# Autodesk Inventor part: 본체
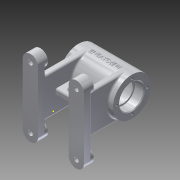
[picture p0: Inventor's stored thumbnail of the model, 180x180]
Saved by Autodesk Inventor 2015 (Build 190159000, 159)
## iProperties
Created: 2015-11
Part Number: 본체
Material: 알루미늄 6061
Document SubType Name: Modeling
Designer: Administrator
Density: 2.7 g/cm^3
Appearance: 알루미늄 - 평지
Author: Administrator
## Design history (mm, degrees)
sketch "스케치8"
  geometry: L1 (40, 40)-(40, -40); L2 (20, 40)-(20, -40); L3 (-20, 40)-(-20, -40); L4 (-40, 40)-(-40, -40); A1 r 10 centre (30, 40) between (40, 40) and (20, 40); A2 r 10 centre (30, -40) between (20, -40) and (40, -40); A3 r 10 centre (-30, 40) between (-20, 40) and (-40, 40); A4 r 10 centre (-30, -40) between (-40, -40) and (-20, -40); 3 further points
  constraints: 8 end point, 8 point on circle, 8 tangent, 4 centre point, 2 parallel, 2 vertical, 1 equal radius, 1 horizontal alignment, 1 vertical alignment
  dimensions: "d54" = 10 radius of A1; "d57" = 0 distance from line of point (40, 0) L1
extrude "돌출3" new body sketch "스케치8" distance "d63" = 10; taper "d64" = 0 deg
sketch "스케치9"
  geometry: L1 (-40, -40)-(-40, 40) reference; L2 (-20, 40)-(-20, -40) reference; L3 (20, -40)-(20, 40) reference; L4 (40, 40)-(40, -40) reference; A1 r 10 centre (-30, 40) between (-20, 40) and (-40, 40) reference; A2 r 10 centre (-30, -40) between (-40, -40) and (-20, -40) reference; A3 r 10 centre (30, -40) between (20, -40) and (40, -40) reference; A4 r 10 centre (30, 40) between (40, 40) and (20, 40) reference; 5 further points
  constraints: 4 coincident, 4 horizontal alignment, 8 other
extrude "돌출4" join sketch "스케치9" distance "d65" = 3; taper "d66" = 0 deg
fillet "모깎기2" dims "d67" = 2
sketch "스케치10"
  geometry: L1 (22, 10)-(38, 10) reference; L2 (40, 8)-(40, 0) reference; L3 (40, 0)-(20, 0) reference; L4 (20, 0)-(20, 8) reference; L5 (-38, 10)-(-22, 10) reference; L6 (-20, 8)-(-20, 0) reference; L7 (-20, 0)-(-40, 0) reference; L8 (-40, 0)-(-40, 8) reference; L9 (0, 0)-(0, 68); L10 (35, 68)-(-35, 68); L11 (-35, 68)-(-35, 93); L12 (-35, 93)-(35, 93); L13 (35, 93)-(35, 68); A1 r 2 centre (22, 8) between (22, 10) and (20, 8) reference; A2 r 2 centre (38, 8) between (40, 8) and (38, 10) reference; A3 r 2 centre (-38, 8) between (-38, 10) and (-40, 8) reference; A4 r 2 centre (-22, 8) between (-20, 8) and (-22, 10) reference
  constraints: 10 end point, 2 perpendicular, 2 vertical
  dimensions: "d70" = 68 distance of L9.start L9.end; "d71" = 35 distance of L9.end L10.start; "d72" = 70 distance of L10.start L10.end; "d73" = 25 distance of L10.end L11.end
revolve "회전1" sketch "스케치10" stored, may be unused: angle "d74" = 90 deg
sketch "스케치11"
  geometry: L1 (-31.34, -58)-(31.34, -58) reference; L2 (31.34, -58)-(31.34, -55) reference; L3 (31.34, -55)-(48.66, -55) reference; L4 (48.66, -55)-(48.66, -68) reference; L5 (48.66, -68)-(-48.66, -68) reference; L6 (-48.66, -68)-(-48.66, -55) reference; L7 (-48.66, -55)-(-31.34, -55) reference; L8 (-31.34, -55)-(-31.34, -58) reference; C1 r 25 at (0, 0) reference; A1 r 20 centre (0, 0) between (-20, 0) and (0, 20); 3 further points
  constraints: 4 point on circle, 1 centre point, 1 coincident
  dimensions: "d75" = 40 diameter of A1
hole "구멍6" sketch "스케치11" at (-20, 0), (0, 20), (20, 0), (0, -20) diameter "d76" = 3.242; stored, may be unused: countersink angle "d80" = 90 deg, drill point angle "d82" = 118 deg; dims "d77" = 8, "d78" = 4, "d79" = 2, "d81" = 10
sketch "스케치12"
  geometry: L1 (-31.34, -58)-(31.34, -58) reference; L2 (31.34, -58)-(31.34, -55) reference; L3 (31.34, -55)-(48.66, -55) reference; L4 (48.66, -55)-(48.66, -68) reference; L5 (48.66, -68)-(-48.66, -68) reference; L6 (-48.66, -68)-(-48.66, -55) reference; L7 (-48.66, -55)-(-31.34, -55) reference; L8 (-31.34, -55)-(-31.34, -58) reference; C1 r 1.621 at (20, 0) reference; C2 r 1.621 at (-20, 0) reference; C3 r 1.621 at (0, 20) reference; C4 r 1.621 at (0, -20) reference; C5 r 25 at (0, 0) reference; 1 further point
hole "구멍7" sketch "스케치12" at (0, 0) diameter "d83" = 32; stored, may be unused: countersink angle "d87" = 90 deg, drill point angle "d89" = 0 deg; dims "d84" = 8, "d85" = 4, "d86" = 2, "d88" = 12
sketch "스케치13"
  geometry: L1 (-32.859, -58)-(32.859, -58) reference; L2 (32.859, -58)-(32.859, -55) reference; L3 (32.859, -55)-(47.141, -55) reference; L4 (47.141, -55)-(47.141, -68) reference; L5 (47.141, -68)-(-47.141, -68) reference; L6 (-47.141, -68)-(-47.141, -55) reference; L7 (-47.141, -55)-(-32.859, -55) reference; L8 (-32.859, -55)-(-32.859, -58) reference; C1 r 16 at (0, 0) reference; C2 r 25 at (0, 0) reference; 1 further point
hole "구멍8" sketch "스케치13" at (0, 0) diameter "d90" = 28; stored, may be unused: countersink angle "d94" = 90 deg, drill point angle "d96" = 0 deg; dims "d91" = 8, "d92" = 4, "d93" = 2, "d95" = 2
sketch "스케치14"
  geometry: L1 (-44.359, -55)-(-35.641, -55) reference; L2 (-35.641, -55)-(-35.641, -58.268) reference; L3 (-35.641, -58.268)-(35.641, -58.268) reference; L4 (35.641, -58.268)-(35.641, -55) reference; L5 (35.641, -55)-(44.359, -55) reference; L6 (44.359, -55)-(44.359, -68) reference; L7 (44.359, -68)-(-44.359, -68) reference; L8 (-44.359, -68)-(-44.359, -55) reference; C1 r 14 at (0, 0) reference; C2 r 25 at (0, 0) reference; 1 further point
hole "구멍9" sketch "스케치14" at (0, 0) diameter "d97" = 42; stored, may be unused: countersink angle "d101" = 90 deg, drill point angle "d103" = 0 deg; dims "d98" = 8, "d99" = 4, "d100" = 2, "d102" = 42
chamfer "모따기3" distance "d104" = 1; stored, may be unused: second distance "d105" = 2, angle "d106" = 45 deg
chamfer "모따기4" distance "d107" = 1; stored, may be unused: second distance "d108" = 2, angle "d109" = 45 deg
fillet "모깎기3" dims "d110" = 3
node "작업 평면5"
  node "작업 평면4"
sketch "스케치15"
  geometry: L1 (35, -25)-(-35, -25) reference; L2 (35, 25)-(35, -25) reference; L3 (35, 25)-(-35, 25) reference; L4 (-35, 25)-(-35, -25) reference; C1 r 5 at (0, 0); 1 further point
  constraints: 1 centre point, 1 coincident
  dimensions: "d112" = 10 diameter of C1
extrude "돌출5" join sketch "스케치15" stored distance "d113" = 70; taper "d114" = 0 deg
fillet "모깎기4" dims "d115" = 2
sketch "스케치16"
  geometry: C1 r 5 at (0, 0) reference; 1 further point
hole "구멍10" sketch "스케치16" at (0, 0) diameter "d116" = 5.188; stored, may be unused: countersink angle "d120" = 90 deg, drill point angle "d122" = 0 deg; dims "d117" = 15, "d118" = 4, "d119" = 2, "d121" = 15
sketch "스케치17"
  geometry: L1 (0, 8)-(80, 8) reference; L2 (80, 0)-(80, 8) reference; L3 (80, 0)-(0, 0) reference; L4 (0, 0)-(0, 8) reference; L5 (0, 8)-(0, 13) reference; L6 (80, 8)-(80, 13) reference; L7 (40, 0)-(15, 0); L8 (80, 0)-(0, 0) reference; L9 (15, 0)-(15, 67); L10 (15, 0)-(65, 0); L11 (65, 0)-(65, 67); L12 (65, 67)-(53.394, 48.192); L13 (53.394, 48.192)-(40, 44.602); L14 (40, 44.602)-(25.54, 50.049); L15 (25.54, 50.049)-(15, 67); C1 r 25 at (40, 68) reference; C2 r 20.236 at (40, 68) reference
  constraints: 16 end point, 2 point on line, 1 perpendicular
  dimensions: "d126" = 50 distance of L7.end L10.end; "d127" = 90 deg angle of L11 L10
extrude "돌출6" join sketch "스케치17" distance "d128" = 8; taper "d129" = 0 deg
fillet "모깎기6" dims "d131" = 2
sketch "스케치18"
  geometry: L1 (8, -65)-(4, -65) reference; L2 (2, -63)-(2, -17) reference; L3 (4, -15)-(8, -15) reference; L4 (10, -17)-(10, -63) reference; L5 (58, -17)-(58, -63) reference; L6 (56, -65)-(52, -65) reference; L7 (50, -63)-(50, -17) reference; L8 (52, -15)-(56, -15) reference; C1 r 10 at (0, 0) reference; C2 r 10 at (0, -80) reference; C3 r 10 at (60, -80) reference; C4 r 10 at (60, 0) reference; A1 r 2 centre (8, -63) between (8, -65) and (10, -63) reference; A2 r 2 centre (4, -63) between (2, -63) and (4, -65) reference; A3 r 2 centre (4, -17) between (4, -15) and (2, -17) reference; A4 r 2 centre (8, -17) between (10, -17) and (8, -15) reference; A5 r 2 centre (56, -17) between (58, -17) and (56, -15) reference; A6 r 2 centre (56, -63) between (56, -65) and (58, -63) reference; A7 r 2 centre (52, -63) between (50, -63) and (52, -65) reference; A8 r 2 centre (52, -17) between (52, -15) and (50, -17) reference; 1 further point
hole "구멍11" sketch "스케치18" at (60, 0), (0, 0) diameter "d132" = 12; stored, may be unused: countersink angle "d136" = 90 deg, drill point angle "d138" = 0 deg; dims "d133" = 3, "d134" = 4, "d135" = 2, "d137" = 4
sketch "스케치19"
  geometry: L1 (8, 15)-(4, 15) reference; L2 (2, 17)-(2, 63) reference; L3 (4, 65)-(8, 65) reference; L4 (10, 63)-(10, 17) reference; L5 (58, 63)-(58, 17) reference; L6 (56, 15)-(52, 15) reference; L7 (50, 17)-(50, 63) reference; L8 (52, 65)-(56, 65) reference; C1 r 6 at (60, 80) reference; C2 r 6 at (0, 80) reference; C3 r 10 at (0, 80) reference; C4 r 10 at (0, 0) reference; C5 r 10 at (60, 0) reference; C6 r 10 at (60, 80) reference; A1 r 2 centre (8, 17) between (8, 15) and (10, 17) reference; A2 r 2 centre (4, 17) between (2, 17) and (4, 15) reference; A3 r 2 centre (4, 63) between (4, 65) and (2, 63) reference; A4 r 2 centre (8, 63) between (10, 63) and (8, 65) reference; A5 r 2 centre (56, 63) between (58, 63) and (56, 65) reference; A6 r 2 centre (56, 17) between (56, 15) and (58, 17) reference; A7 r 2 centre (52, 17) between (50, 17) and (52, 15) reference; A8 r 2 centre (52, 63) between (52, 65) and (50, 63) reference; 1 further point
hole "구멍12" sketch "스케치19" at (0, 0), (60, 0) diameter "d139" = 12; stored, may be unused: countersink angle "d143" = 90 deg, drill point angle "d145" = 0 deg; dims "d140" = 3, "d141" = 4, "d142" = 2, "d144" = 4
node "작업 평면11"
sketch "스케치20"
  geometry: L1 (-9.732, -77.701)-(-9.732, -2.299) reference; L2 (9.732, -2.299)-(9.732, -16) reference; L3 (10, -17)-(10, -63) reference; L4 (9.732, -64)-(9.732, -77.701) reference; L5 (69.732, -2.299)-(69.732, -77.701) reference; L6 (50.268, -77.701)-(50.268, -64) reference; L7 (50, -63)-(50, -17) reference; L8 (50.268, -16)-(50.268, -2.299) reference; C1 r 6 at (0, -80) reference; C2 r 6 at (60, -80) reference; C3 r 6 at (60, 0) reference; C4 r 6 at (0, 0) reference; A1 r 10 centre (0, 0) between (9.732, -2.299) and (-9.732, -2.299) reference; A2 r 2 centre (8, -17) between (10, -17) and (9.732, -16) reference; A3 r 2 centre (8, -63) between (9.732, -64) and (10, -63) reference; A4 r 10 centre (0, -80) between (-9.732, -77.701) and (9.732, -77.701) reference; A5 r 10 centre (60, -80) between (50.268, -77.701) and (69.732, -77.701) reference; A6 r 2 centre (52, -63) between (50, -63) and (50.268, -64) reference; A7 r 2 centre (52, -17) between (50.268, -16) and (50, -17) reference; A8 r 10 centre (60, 0) between (69.732, -2.299) and (50.268, -2.299) reference; 5 further points
hole "구멍13" sketch "스케치20" at (0, 0), (60, 0), (60, -80), (0, -80) diameter "d147" = 6; stored, may be unused: countersink angle "d151" = 90 deg, drill point angle "d153" = 0 deg; dims "d148" = 3, "d149" = 4, "d150" = 2, "d152" = 15
fillet "모깎기8" dims "d174" = 2
sketch "스케치23"
  geometry: L1 (-24.026, 88)-(-25, 89.621) reference; L2 (-25, 89.621)-(-35, 89.621) reference; L3 (-35, 89.621)-(-35, 93) reference; L4 (-35, 93)-(-7, 93) reference; L5 (-5, 95)-(-5, 96) reference; L6 (-5, 96)-(-2.594, 96) reference; L7 (-2.594, 96)-(-2.594, 89) reference; L8 (2.594, 89)-(2.594, 96) reference; L9 (2.594, 96)-(5, 96) reference; L10 (5, 96)-(5, 95) reference; L11 (7, 93)-(35, 93) reference; L12 (35, 93)-(35, 89.621) reference; L13 (35, 89.621)-(25, 89.621) reference; L14 (25, 89.621)-(24.026, 88) reference; L15 (24.026, 88)-(25, 86.379) reference; L16 (25, 86.379)-(35, 86.379) reference; L17 (35, 86.379)-(35, 85) reference; L18 (35, 85)-(34, 84) reference; L19 (34, 84)-(23, 84) reference; L20 (23, 84)-(23, 82) reference; L21 (23, 82)-(21, 82) reference; L22 (21, 82)-(21, 86) reference; L23 (18, 89)-(2.594, 89) reference; L24 (-21, 86)-(-21, 82) reference; L25 (-21, 82)-(-23, 82) reference; L26 (-23, 82)-(-23, 84) reference; L27 (-23, 84)-(-34, 84) reference; L28 (-34, 84)-(-35, 85) reference; L29 (-35, 85)-(-35, 86.379) reference; L30 (-35, 86.379)-(-25, 86.379) reference; L31 (-25, 86.379)-(-24.026, 88) reference; L32 (-24.026, 48)-(-25, 49.621) reference; L33 (-25, 49.621)-(-35, 49.621) reference; L34 (-35, 49.621)-(-35, 51) reference; L35 (-35, 51)-(-34, 52) reference; L36 (-34, 52)-(-23, 52) reference; L37 (-23, 52)-(-23, 54) reference; L38 (-23, 54)-(-21, 54) reference; L39 (-21, 54)-(-21, 50) reference; L40 (-18, 47)-(18, 47) reference; L41 (21, 50)-(21, 54) reference; L42 (21, 54)-(23, 54) reference; L43 (23, 54)-(23, 52) reference; L44 (23, 52)-(34, 52) reference; L45 (34, 52)-(35, 51) reference; L46 (35, 51)-(35, 49.621) reference; L47 (35, 49.621)-(25, 49.621) reference; L48 (25, 49.621)-(24.026, 48) reference; L49 (24.026, 48)-(25, 46.379) reference; L50 (25, 46.379)-(35, 46.379) reference; L51 (35, 46.379)-(35, 43) reference; L52 (35, 43)-(28, 43) reference; L53 (28, 43)-(28, 10) reference; L54 (28, 10)-(38, 10) reference; L55 (40, 8)-(40, 0) reference; L56 (40, 0)-(20, 0) reference; L57 (20, 0)-(20, 41) reference; L58 (18, 43)-(-18, 43) reference; L59 (-20, 41)-(-20, 0) reference; L60 (-20, 0)-(-40, 0) reference; L61 (-40, 0)-(-40, 8) reference; L62 (-38, 10)-(-28, 10) reference; L63 (-28, 10)-(-28, 43) reference; L64 (-28, 43)-(-35, 43) reference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; A1 r 3 centre (18, 86) between (21, 86) and (18, 89) reference; A2 r 3 centre (-18, 86) between (-18, 89) and (-21, 86) reference; A3 r 3 centre (-18, 50) between (-21, 50) and (-18, 47) reference; A4 r 3 centre (18, 50) between (18, 47) and (21, 50) reference; A5 r 2 centre (38, 8) between (40, 8) and (38, 10) reference; A6 r 2 centre (18, 41) between (20, 41) and (18, 43) reference; A7 r 2 centre (-18, 41) between (-18, 43) and (-20, 41) reference; A8 r 2 centre (-38, 8) between (-38, 10) and (-40, 8) reference; 1 further point
  constraints: 10 end point, 2 collinear, 2 perpendicular, 2 point on line, 1 horizontal, 1 parallel, 2 other
  dimensions: "d175" = 20 distance of L69.start L69.end; "d176" = 90 deg angle of L69 L70 (derived)
extrude "돌출8" join sketch "스케치23" stored distance "d177" = 8; taper "d178" = 0 deg
fillet "모깎기9" dims "d185" = 2
fillet "모깎기10" dims "d186" = 2
node "작업 평면6"
node "작업 평면7"
sketch "스케치25"
  geometry: L1 (-38, 10)-(-22, 10) reference; L2 (-20, 8)-(-20, 0) reference; L3 (-20, 0)-(-40, 0) reference; L4 (-40, 0)-(-40, 8) reference; L5 (22, 10)-(38, 10) reference; L6 (40, 8)-(40, 0) reference; L7 (40, 0)-(20, 0) reference; L8 (20, 0)-(20, 8) reference; L9 (-35, 43)-(-35, 93) reference; L10 (35, 43)-(35, 93) reference; L11 (-35, 93)-(35, 93) reference; A1 r 2 centre (-38, 8) between (-38, 10) and (-40, 8) reference; A2 r 2 centre (-22, 8) between (-20, 8) and (-22, 10) reference; A3 r 2 centre (38, 8) between (40, 8) and (38, 10) reference; A4 r 2 centre (22, 8) between (22, 10) and (20, 8) reference; 3 further points
  constraints: 1 coincident, 1 other
feature "엠보싱1" sketch "스케치25" dims "d190" = 0.5, "d191" = 0
node "작업축1"
node "작업 평면10"
  node "작업 평면9"
sketch "스케치28"
  geometry: 1 further point
sketch "스케치29"
  geometry: L1 (35, 51.477)-(35, 43.322) reference; L2 (35, 43.322)-(28, 43.322) reference; L3 (28, 43.322)-(28, 10) reference; L4 (28, 10)-(38, 10) reference; L5 (40, 8)-(40, 0) reference; L6 (40, 0)-(20, 0) reference; L7 (20, 0)-(20, 25) reference; L8 (-20, 25)-(20, 25) reference; L9 (-20, 41)-(-20, 25) reference; L10 (20, 41)-(-20, 41) reference; L11 (20, 41)-(20, 41.298) reference; L12 (18, 43.322)-(-18, 43.322) reference; L13 (-20, 41.298)-(-20, 41) reference; L14 (23, 52.508)-(34, 52.508) reference; L15 (23, 54.584)-(23, 52.508) reference; L16 (21, 54.584)-(23, 54.584) reference; L17 (21, 50.45)-(21, 54.584) reference; L18 (-18, 47.384)-(18, 47.384) reference; L19 (-21, 54.584)-(-21, 50.45) reference; L20 (-23, 54.584)-(-21, 54.584) reference; L21 (-23, 52.508)-(-23, 54.584) reference; L22 (-34, 52.508)-(-23, 52.508) reference; L23 (-35, 43.322)-(-35, 51.477) reference; L24 (-28, 43.322)-(-35, 43.322) reference; L25 (-28, 10)-(-28, 43.322) reference; L26 (-38, 10)-(-28, 10) reference; L27 (-40, 0)-(-40, 8) reference; L28 (-20, 0)-(-40, 0) reference; L29 (-20, 25)-(-20, 0) reference; L30 (20, 25)-(20, 41) reference; L31 (34, 83.492)-(23, 83.492) reference; L32 (23, 83.492)-(23, 81.416) reference; L33 (23, 81.416)-(21, 81.416) reference; L34 (21, 81.416)-(21, 85.55) reference; L35 (18, 88.616)-(-18, 88.616) reference; L36 (-21, 85.55)-(-21, 81.416) reference; L37 (-21, 81.416)-(-23, 81.416) reference; L38 (-23, 81.416)-(-23, 83.492) reference; L39 (-23, 83.492)-(-34, 83.492) reference; L40 (-35, 84.523)-(-35, 92.678) reference; L41 (-35, 92.678)-(-5.508, 92.678) reference; L42 (-3, 94.413)-(-3, 96) reference; L43 (-3, 96)-(3, 96) reference; L44 (3, 96)-(3, 94.413) reference; L45 (5.508, 92.678)-(35, 92.678) reference; L46 (35, 92.678)-(35, 84.523) reference; L47 (-20, 0)-(-20, 33); L48 (-20, 8)-(-20, 53.858) reference; L49 (-8, 36.5)-(8, 36.5); L50 (-8, 29.5)-(8, 29.5); A1 r 2 centre (38, 8) between (40, 8) and (38, 10) reference; A2 r 2 centre (-38, 8) between (-38, 10) and (-40, 8) reference; A3 r 3.5 centre (-8, 33) between (-8, 36.5) and (-8, 29.5); A4 r 3.5 centre (8, 33) between (8, 29.5) and (8, 36.5); 1 further point
  constraints: 6 end point, 4 point on circle, 2 centre point, 1 point on line, 1 tangent, 12 other
  dimensions: "d206" = 33 distance of L28.start L47.end
extrude "돌출11" cut sketch "스케치29" distance "d211" = 8; taper "d212" = 0 deg
fillet "모깎기12" dims "d213" = 2
fillet "모깎기13" dims "d214" = 2
fillet "모깎기14" dims "d215" = 2
fillet "모깎기15" dims "d216" = 2
fillet "모깎기16" dims "d220" = 0.3
chamfer "모따기8" distance "d221" = 1; stored, may be unused: second distance "d222" = 2, angle "d223" = 45 deg
chamfer "모따기9" distance "d224" = 1; stored, may be unused: second distance "d225" = 2, angle "d226" = 45 deg
chamfer "모따기10" distance "d227" = 1; stored, may be unused: second distance "d228" = 2, angle "d229" = 45 deg
chamfer "모따기11" distance "d230" = 1; stored, may be unused: second distance "d231" = 2, angle "d232" = 45 deg
fillet "모깎기17" dims "d233" = 0.3
node "작업 평면12"
  node "작업축2"
node "작업 평면13"
node "솔리드2"
mirror "대칭4"
mirror "대칭5"
mirror "대칭6"
mirror "대칭7"
node "작업 평면8"
node "절단 모서리 투영2"
node "절단 모서리 투영3"
node "절단 모서리 투영4"
node "절단 모서리 투영5"
node "절단 모서리 투영6"
node "절단 모서리 투영7"
node "절단 모서리 투영8"
node "절단 모서리 투영9"
node "절단 모서리 투영10"
node "절단 모서리 투영11"
node "절단 모서리 투영12"
node "절단 모서리 투영15"
node "절단 모서리 투영17"
node "절단 모서리 투영20"
other parameters: "d111" = 3, "d165" = 11.5, "d172" = 3.5, "d173" = 3.5, "d187" = 25.5, "d192" = 30 deg, "d193" = -60 deg, "d194" = -28, "d234" = 30 deg
